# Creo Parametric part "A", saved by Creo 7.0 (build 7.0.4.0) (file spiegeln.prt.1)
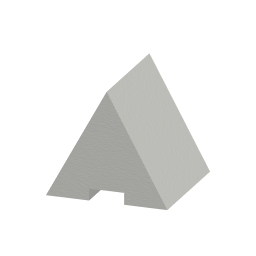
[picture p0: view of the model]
Materials in the file: S235JRG2

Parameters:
  PTC_MATERIAL_NAME = "S235JRG2"
  BENENNUNG = "XXX"
  DATUM = "XX.XX.XX"
  ERSTELLER = "ARINDA"
  TEILETYP = "Fertigungsteil"
  SELECT_EN_NAME = "S235JRG2"
  SELECT_DIN_NAME = "RSt37-2"
  SELECT_DIN_NUMBER = "1.0038"
  SELECT_ASTM_NAME = "A 283 M Grade 2"
  MATERIAL_GROUP = "ME_ST_Baustahl"
  STANDARD_EN_DELIVERYSPEC = "DIN EN 10025"
  STANDARD_DIN_DELIVERYSPEC = "DIN 17100"

Other parameters: MASSE

Created from: ARINDA-STARTTEIL.PRT

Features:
  1. coordinate system "CS0"
  2. datum plane "DTM1", "T_RECHTS_Y-Z"
  3. datum plane "DTM2", "T_OBEN_X-Z"
  4. datum plane "DTM3", "T_VORNE_X-Y"
  5. datum axis "T_X-ACHSE"
  6. datum axis "A_1"
  7. datum axis "A_2"
  8. extrusion "Profil 1"

Other named items: T_BASIC, T_Y-ACHSE, T_Z-ACHSE

Layers: 00_STD-ACHSEN, 00_STD-EBENEN, 00_STD-KOORDSYS, VOLUMENGEOMETRIE

Surfaces: 9 plane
